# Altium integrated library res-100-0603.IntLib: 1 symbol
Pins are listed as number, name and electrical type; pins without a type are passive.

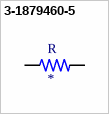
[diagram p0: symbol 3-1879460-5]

## 3-1879460-5
designator R
RES 0.27 OHM 1% 1/10W 0603; Resistance: 27; MF: TE Connectivity; Power_Rating: .1 W; MP: 3-1879460-5
footprint RESC1608X50N
pins: 1, 2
